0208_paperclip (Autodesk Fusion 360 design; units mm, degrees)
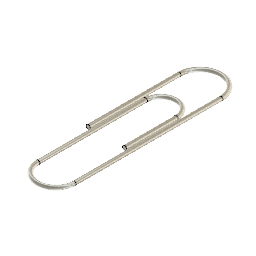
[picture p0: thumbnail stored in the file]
sketch "Sweep Path" plane through (0, 0, 0) normal (0, 0, 1) x axis (1, 0, 0)
  line L1 (0, 16.25) -> (0, 0)
  line L2 (7.5, 16.25) -> (0, 16.25)
  line L3 (7.5, -10) -> (7.5, 16.25)
  line L4 (1, -10) -> (7.5, -10)
  line L5 (1, 9.25) -> (1, -10)
  line L6 (6.5, 9.25) -> (1, 9.25)
  line L7 (6.5, 0) -> (6.5, 9.25)
  arc A1 centre (3.75, 16.25) radius 3.75 clockwise from (0, 16.25) to (7.5, 16.25)
  arc A2 centre (3.75, 9.25) radius 2.75 clockwise from (1, 9.25) to (6.5, 9.25)
  arc A3 centre (4.25, -10) radius 3.25 clockwise from (7.5, -10) to (1, -10)
  point P1 (0, 0)
  point P2 (0, 0)
  point P3 (0, 16.25)
  point P4 (7.5, 16.25)
  point P5 (7.5, -10)
  point P6 (1, -10)
  point P7 (1, 9.25)
  point P8 (6.5, 9.25)
  point P9 (6.5, 0)
  coincident P1 P2
  vertical L1
  perpendicular L1 L2
  perpendicular L2 L3
  perpendicular L3 L4
  perpendicular L4 L5
  perpendicular L5 L6
  perpendicular L6 L7
  tangent L1 A1
  tangent L5 A2
  tangent L5 A3
  dimension "d1" distance P2 P3 = 16.25
  dimension "d2" distance P3 P4 = 7.5
  dimension "d3" distance P4 P5 = 26.25
  dimension "d4" distance P5 P6 = 6.5
  dimension "d5" distance P6 P7 = 19.25
  dimension "d6" distance P7 P8 = 5.5
  dimension "d7" distance P8 P9 = 9.25
sketch "Sweep Profile" plane through (0, 0, 0) normal (0, 1, 0) x axis (1, 0, 0)
  circle C1 centre (0, 0) radius 0.375
  point P1 (0, 0)
  point P2 (0, 0)
  coincident P1 P2
  dimension "d8" diameter C1 = 0.75
sweep "Sweep1" sketch "Sweep Profile" TwistAngle 0 TaperAngle 0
